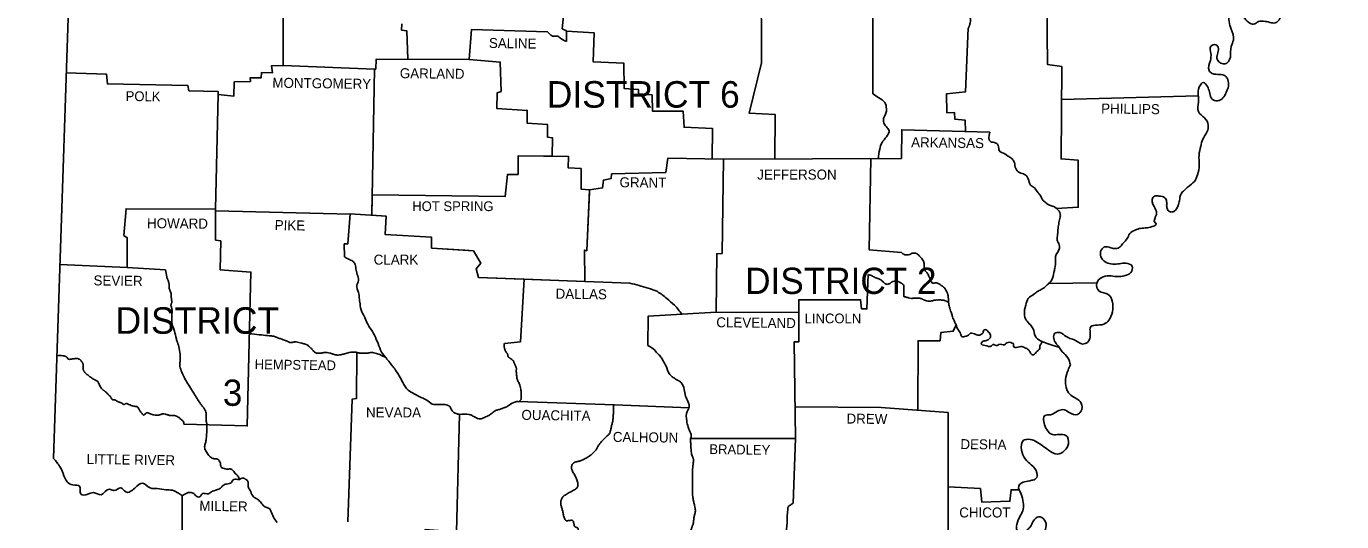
# Model space of a CAD drawing. Extents: x 541267 to 698737, y 790528 to 880942.
# Drawn here: x 637378 to 660525, y 843520 to 852235 of the extents above; entities that cross this region are included whole.
import ezdxf

# ---------------------------------------------------------------- set-up
doc = ezdxf.new("R2010")
doc.units = 0
doc.layers.add('Default', color=7, linetype='Continuous')
doc.layers.add('R_Draft', color=7, linetype='Continuous')

msp = doc.modelspace()

# ---------------------------------------------------------------- linework, layer by layer
at = {"layer": 'Default'}
msp.add_line((643463, 849273), (643456, 848913), dxfattribs=at)
for points in [[(647287, 849322), (647289, 849359), (647141, 849371), (647141, 849731), (646912, 849748), (646920, 849944), (646634, 849948), (646036, 849957), (646032, 849629), (645848, 849629), (645803, 849240), (643463, 849273)], [(647207, 847747), (647203, 848299), (647240, 848287), (647287, 849322)], [(647287, 849322), (647287, 849322)], [(643456, 848913), (643708, 848897), (643692, 848573), (644506, 848528), (644510, 848332), (645097, 848296), (645247, 848287)], [(645247, 848287), (645374, 848066), (645296, 847968), (645333, 847816), (646137, 847787), (647207, 847747)]]:
    msp.add_lwpolyline(points, dxfattribs=at)
at = {"layer": 'R_Draft'}
for p, q in [((643504, 851483), (643456, 848913)), ((655370, 847710), (656219, 847723))]:
    msp.add_line(p, q, dxfattribs=at)
for points in [[(637378, 862535), (638225, 855734), (637857, 844633)], [(641905, 853220), (641899, 851544), (641695, 851540), (641711, 851417), (641515, 851421), (641511, 851331), (641318, 851331), (641323, 851266), (641036, 851258), (641032, 851008), (640754, 851033), (640709, 849019), (639133, 849024), (639096, 848557), (639154, 848516), (639150, 847992), (637970, 848044)], [(651687, 853361), (651696, 852629), (652273, 852616), (652277, 851045)], [(650071, 853173), (650308, 853156), (650313, 851593), (650100, 850705), (650554, 850685), (650550, 849903)], [(648177, 852764), (647882, 852796), (647894, 852686), (647358, 852665), (647342, 852506), (646838, 852477), (646810, 852191), (646884, 852154), (646884, 851966)], [(655508, 849028), (655890, 849052), (655886, 849883), (655587, 849903), (655603, 851528), (655346, 851565), (655338, 852657), (658848, 852682)], [(643986, 852281), (643982, 852170), (644076, 852154), (644094, 851656)], [(646548, 852137), (645210, 852178), (645173, 851651), (643536, 851659), (643530, 851482)], [(646884, 852152), (647370, 852121), (647354, 851610), (647890, 851589), (647898, 851143), (648152, 851123), (648152, 851045), (648389, 851029), (648398, 850742), (648938, 850742), (648954, 850460), (649453, 850435), (649449, 849903)], [(653954, 852203), (653905, 851082), (653570, 851045), (653578, 850714), (653713, 850718), (653717, 850603), (653901, 850583), (653907, 850385)], [(645173, 851651), (645717, 851606), (645734, 851090), (645664, 851065), (645656, 850791), (646192, 850754), (646192, 850529), (646548, 850509), (646552, 850284), (646638, 850272), (646634, 849948)], [(638082, 851417), (638790, 851393), (638806, 851221), (640222, 851192), (640238, 851102), (640754, 851086), (640754, 851033)], [(643504, 851483), (641899, 851544)], [(643530, 851482), (643504, 851483)], [(655598, 850950), (658002, 851010)], [(654331, 850374), (652784, 850415), (652776, 849912), (649646, 849899)], [(643463, 849273), (645803, 849240), (645848, 849629), (646032, 849629), (646036, 849957), (646920, 849944), (646912, 849748), (647141, 849731), (647141, 849371), (647289, 849359), (647287, 849322)], [(647289, 849359), (647518, 849392), (647534, 849531), (647669, 849556), (647677, 849637), (648631, 849666), (648668, 849916), (649646, 849899)], [(649646, 849899), (649621, 848238), (649527, 848234), (649515, 847207)], [(652241, 849909), (652207, 848303), (652776, 848258)], [(647289, 849359), (647240, 848287), (647203, 848299), (647207, 847747)], [(640709, 849019), (640709, 848475), (640799, 848459), (640791, 847952), (641331, 847911), (641265, 845206), (640152, 845235)], [(640709, 848991), (643077, 848929)], [(642980, 848181), (642972, 848406), (643037, 848410), (643078, 848938), (643708, 848897), (643692, 848573), (644506, 848528), (644510, 848332), (645247, 848287), (645374, 848066), (645296, 847968), (645333, 847816), (648001, 847718)], [(639150, 847992), (639829, 847952)], [(646137, 847787), (646073, 846687), (645791, 846654)], [(652195, 847866), (652170, 847264), (652076, 847264), (652060, 847424), (650971, 847424), (650973, 847199)], [(649515, 847207), (648916, 847170)], [(649515, 847207), (650973, 847199)], [(650973, 847199), (650975, 846687), (650890, 846683), (650914, 844985)], [(648919, 847170), (648320, 847133), (648316, 846622)], [(653738, 846982), (653688, 846871), (653472, 846851), (653459, 846703), (653071, 846703), (653066, 845480)], [(643197, 846497), (643188, 845685), (643115, 845676), (643033, 843520)], [(655252, 846691), (655343, 846655), (655448, 846619), (655548, 846593)], [(646032, 845636), (647726, 845574), (649041, 845523)], [(645001, 845406), (644948, 843344), (644396, 843381), (644391, 843229), (643663, 843272)], [(650902, 845541), (652420, 845529), (653598, 845439)], [(653598, 845439), (653598, 842992), (653631, 840642)], [(649065, 844981), (650914, 844985)], [(650914, 844985), (650873, 843847), (650783, 843790)], [(640119, 843974), (640128, 840664), (655125, 840639)], [(653598, 844135), (654167, 844101), (654192, 843864), (654687, 843880), (654707, 844081), (654860, 844081)]]:
    msp.add_lwpolyline(points, dxfattribs=at)
for points in [[(660346, 855747), (660362, 855628), (660293, 855501), (660268, 855374), (660281, 855247), (660150, 855178), (660035, 855096), (660101, 854998), (660223, 854908), (660346, 854838), (660424, 854769), (660444, 854601), (660465, 854494), (660506, 854347), (660522, 854245), (660448, 854122), (660362, 854097), (660272, 854126), (660166, 854134), (660080, 854052), (660019, 853938), (659957, 853823), (659912, 853725), (659867, 853619), (659777, 853496), (659667, 853476), (659536, 853443), (659458, 853353), (659470, 853201), (659544, 853099), (659601, 852972), (659642, 852862), (659622, 852723), (659565, 852620), (659491, 852559), (659458, 852428), (659405, 852330), (659356, 852297), (659258, 852305), (659151, 852326), (659061, 852318), (658975, 852273), (658889, 852301), (658799, 852399), (658726, 852473), (658644, 852502), (658558, 852457), (658542, 852322), (658582, 852183), (658619, 851994), (658582, 851880), (658570, 851691)], [(653909, 852596), (653905, 852586), (653901, 852576), (653896, 852555), (653893, 852534), (653893, 852524), (653893, 852514), (653896, 852492), (653903, 852470), (653913, 852449), (653919, 852438), (653926, 852428), (653931, 852422), (653939, 852418), (653956, 852414), (653972, 852410), (653979, 852406), (653981, 852403), (653983, 852399), (653985, 852394), (653987, 852389), (653993, 852358), (653994, 852338), (653993, 852328), (653991, 852318), (653983, 852276), (653978, 852256), (653975, 852246), (653971, 852236), (653963, 852219), (653954, 852203)], [(646884, 851966), (646777, 852027), (646716, 852064), (646650, 852060), (646597, 852092), (646548, 852137)], [(658570, 851691), (658476, 851573), (658337, 851646), (658337, 851745), (658357, 851847), (658308, 851912), (658222, 851884), (658222, 851757), (658214, 851634), (658190, 851458), (658247, 851405), (658378, 851389), (658472, 851364), (658529, 851270), (658525, 851155), (658480, 851045), (658415, 850955), (658312, 850922), (658231, 850975), (658198, 851082), (658161, 851176), (658091, 851245), (658018, 851168), (658001, 851025), (658005, 850902), (658005, 850734), (658112, 850623), (658177, 850497), (658157, 850382), (658079, 850247), (658046, 850128), (658014, 849969), (658018, 849793), (657989, 849621), (657932, 849506), (657825, 849412), (657756, 849351), (657699, 849290), (657670, 849167), (657649, 849081), (657572, 848979), (657510, 848970), (657461, 849011), (657445, 849081), (657445, 849150), (657412, 849220), (657310, 849249), (657228, 849245), (657191, 849187), (657244, 849028), (657265, 848925), (657236, 848786), (657253, 848770), (657105, 848692), (656987, 848680), (656888, 848651), (656794, 848590), (656749, 848500), (656684, 848426), (656626, 848357), (656549, 848324), (656463, 848340), (656348, 848353), (656283, 848271), (656303, 848152), (656381, 848082), (656496, 848050), (656614, 848058), (656729, 848070), (656835, 848013), (656815, 847902), (656712, 847849), (656561, 847833), (656438, 847845), (656291, 847812), (656217, 847718), (656258, 847575), (656418, 847518), (656491, 847383), (656496, 847256), (656442, 847088), (656369, 847010), (656225, 846978), (656115, 846957), (656099, 846769), (656050, 846675), (655964, 846646), (655841, 846708), (655767, 846736), (655677, 846777), (655563, 846847), (655477, 846834), (655501, 846654), (655509, 846646), (655608, 846511), (655706, 846405), (655751, 846278)], [(652277, 851045), (652379, 850975), (652485, 850894), (652514, 850783), (652506, 850705), (652473, 850640), (652465, 850538), (652514, 850464), (652559, 850403), (652514, 850292), (652436, 850190), (652395, 850075), (652367, 849903)], [(654331, 850374), (654343, 850206), (654441, 850182), (654482, 850137), (654503, 850042), (654572, 850002), (654666, 849944), (654724, 849903), (654765, 849838), (654789, 849731), (654855, 849662), (654945, 849629), (655010, 849551), (655051, 849441), (655117, 849392), (655182, 849306), (655215, 849269), (655272, 849171), (655329, 849122), (655370, 849093), (655436, 849073), (655518, 849019), (655571, 848938), (655571, 848876), (655550, 848782), (655534, 848684), (655526, 848573), (655518, 848475), (655554, 848393), (655534, 848271), (655493, 848205), (655489, 848115), (655477, 847980), (655460, 847902), (655423, 847776), (655370, 847710)], [(642980, 848181), (643045, 848140), (643123, 848103), (643164, 848042), (643180, 847947), (643209, 847845), (643217, 847739), (643193, 847681), (643225, 847551), (643238, 847460), (643250, 847354), (643283, 847211), (643336, 847113), (643385, 846994), (643467, 846867), (643536, 846728), (643569, 846654), (643630, 846503), (643708, 846401), (643831, 846245), (643941, 846086), (644003, 845967), (644097, 845836), (644203, 845771), (644338, 845701), (644424, 845660), (644522, 845590), (644649, 845582), (644743, 845582), (644829, 845545), (644870, 845472), (644944, 845423), (645001, 845406)], [(652776, 848258), (652837, 848217), (652923, 848222), (652981, 848246), (653026, 848242), (653087, 848205), (653128, 848156), (653156, 848119), (653177, 848062), (653177, 848009), (653197, 847935), (653222, 847906), (653255, 847853), (653275, 847804), (653287, 847771), (653332, 847718), (653373, 847722), (653410, 847718), (653459, 847690), (653533, 847632), (653545, 847616), (653594, 847510), (653603, 847444), (653611, 847358), (653627, 847276), (653660, 847186), (653676, 847125), (653713, 847039), (653738, 846982), (653770, 846908), (653819, 846826), (653840, 846777), (653909, 846781), (653959, 846802), (653995, 846834), (654040, 846830), (654089, 846814), (654155, 846802), (654196, 846826), (654216, 846843), (654220, 846879), (654257, 846900), (654298, 846871), (654343, 846806), (654343, 846765), (654327, 846740), (654274, 846708), (654200, 846683), (654179, 846654), (654249, 846622), (654360, 846613), (654388, 846638), (654462, 846618), (654490, 846638), (654589, 846634), (654634, 846667), (654724, 846663), (654752, 846642), (654752, 846605), (654826, 846589), (654879, 846601), (654949, 846581), (655010, 846548), (655043, 846503), (655084, 846454), (655121, 846466), (655149, 846503), (655211, 846568), (655211, 846609), (655227, 846638), (655252, 846691)], [(639829, 847952), (639849, 847829), (639857, 847802), (639867, 847775), (639878, 847749), (639886, 847722), (639889, 847702), (639889, 847681), (639889, 847661), (639890, 847641), (639898, 847610), (639910, 847579), (639921, 847549), (639927, 847518), (639927, 847473), (639930, 847450), (639933, 847428), (639937, 847405), (639939, 847383), (639937, 847370), (639931, 847358), (639926, 847346), (639923, 847334), (639927, 847309), (639934, 847285), (639941, 847260), (639944, 847235), (639939, 847162), (639939, 847100), (639944, 846998), (639949, 846975), (639958, 846953), (639968, 846931), (639976, 846908), (640009, 846773), (640029, 846703), (640062, 846597), (640083, 846466), (640087, 846368), (640085, 846345), (640082, 846323), (640079, 846300), (640079, 846278), (640103, 846176), (640148, 846073), (640205, 845975), (640275, 845865), (640324, 845779), (640385, 845685), (640435, 845607), (640452, 845582), (640471, 845558), (640490, 845534), (640508, 845509), (640541, 845427), (640543, 845398), (640542, 845369), (640540, 845341), (640541, 845312), (640545, 845286), (640550, 845259), (640555, 845233), (640557, 845206), (640553, 845087), (640545, 844981), (640539, 844944), (640530, 844907), (640522, 844870), (640516, 844834), (640537, 844764), (640615, 844662), (640664, 844633), (640685, 844628), (640707, 844627), (640729, 844625), (640750, 844617), (640774, 844590), (640791, 844559), (640797, 844538), (640798, 844514), (640802, 844492), (640807, 844482), (640815, 844473), (640857, 844453), (640901, 844445), (640913, 844444), (640926, 844444), (640951, 844447), (640975, 844446), (640995, 844437), (641040, 844387), (641102, 844322), (641132, 844264)], [(648001, 847718), (648320, 847628), (648483, 847567), (648647, 847448), (648782, 847330), (648916, 847170)], [(652195, 847866), (652214, 847862), (652232, 847856), (652269, 847841), (652282, 847834), (652295, 847827), (652308, 847819), (652322, 847812), (652339, 847806), (652357, 847801), (652375, 847795), (652391, 847788), (652414, 847772), (652436, 847755), (652452, 847742), (652467, 847728), (652482, 847714), (652490, 847708), (652498, 847702), (652515, 847696), (652534, 847697), (652553, 847703), (652571, 847710), (652585, 847718), (652597, 847727), (652610, 847736), (652625, 847743), (652678, 847751), (652719, 847747), (652764, 847722), (652790, 847707), (652803, 847698), (652808, 847692), (652810, 847689), (652813, 847686), (652821, 847659), (652821, 847646), (652821, 847632), (652821, 847571), (652821, 847485), (652824, 847479), (652831, 847476), (652850, 847473), (652900, 847457), (652952, 847448), (652969, 847449), (652987, 847450), (653004, 847451), (653021, 847452), (653054, 847453), (653087, 847452), (653114, 847448), (653127, 847445), (653140, 847440), (653152, 847434), (653163, 847427), (653174, 847421), (653185, 847415), (653218, 847407), (653267, 847399), (653308, 847403), (653325, 847407), (653343, 847413), (653360, 847418), (653377, 847420), (653418, 847420), (653484, 847420), (653504, 847418), (653515, 847417), (653525, 847415), (653569, 847399), (653589, 847387), (653609, 847373)], [(655370, 847710), (655256, 847616), (655182, 847575), (655104, 847518), (655010, 847448), (654965, 847330), (654941, 847166), (654973, 847068), (655047, 846982), (655096, 846912), (655133, 846789), (655223, 846703), (655252, 846691)], [(641304, 846826), (641478, 846810), (641621, 846794), (641677, 846789), (641704, 846786), (641718, 846784), (641732, 846781), (641761, 846773), (641790, 846762), (641846, 846740), (641949, 846703), (641965, 846697), (641981, 846689), (641997, 846681), (642014, 846675), (642041, 846672), (642069, 846677), (642097, 846683), (642125, 846683), (642172, 846674), (642219, 846663), (642273, 846648), (642300, 846639), (642312, 846633), (642325, 846626), (642366, 846593), (642403, 846556), (642415, 846543), (642425, 846529), (642452, 846503), (642475, 846491), (642498, 846484), (642546, 846483), (642565, 846485), (642585, 846489), (642604, 846493), (642624, 846495), (642718, 846487), (642745, 846479), (642771, 846469), (642797, 846460), (642824, 846454), (642846, 846452), (642867, 846452), (642910, 846458), (642980, 846474), (643062, 846495), (643113, 846503), (643138, 846504), (643164, 846503), (643183, 846500), (643203, 846495), (643222, 846490), (643242, 846487), (643293, 846483), (643344, 846483), (643374, 846485), (643403, 846490), (643433, 846494), (643448, 846495), (643463, 846495), (643493, 846491), (643582, 846465), (643640, 846440), (643697, 846415)], [(645791, 846654), (645786, 846616), (645788, 846596), (645791, 846577), (645796, 846558), (645802, 846539), (645810, 846521), (645820, 846503), (645826, 846494), (645834, 846486), (645842, 846479), (645848, 846470), (645852, 846457), (645853, 846443), (645854, 846429), (645857, 846422), (645861, 846417), (645869, 846410), (645879, 846404), (645888, 846399), (645897, 846393), (645905, 846387), (645912, 846381), (645927, 846370), (645940, 846358), (645946, 846351), (645951, 846343), (645959, 846326), (645966, 846309), (645972, 846291), (645979, 846274), (645990, 846252), (645995, 846241), (645998, 846235), (646000, 846229), (646002, 846215), (646001, 846200), (646000, 846186), (646000, 846172), (646002, 846143), (646004, 846114), (646007, 846079), (646009, 846062), (646012, 846045), (646021, 846013), (646035, 845983), (646050, 845953), (646061, 845922), (646073, 845873), (646081, 845832), (646086, 845762), (646086, 845742), (646087, 845721), (646086, 845701), (646086, 845691), (646086, 845681), (646082, 845669), (646074, 845656), (646052, 845635)], [(648316, 846622), (648410, 846560), (648488, 846478), (648545, 846417), (648582, 846347), (648631, 846266), (648700, 846110), (648762, 846057), (648848, 846004), (648901, 845967), (648954, 845848), (648979, 845730), (649024, 845623), (649044, 845541), (649007, 845460), (648999, 845296), (649024, 845185), (649056, 845104), (649077, 845009), (649065, 844981)], [(637917, 846439), (637958, 846443), (638000, 846442), (638040, 846437), (638073, 846429), (638088, 846418), (638102, 846399), (638117, 846382), (638135, 846376), (638172, 846380), (638237, 846388), (638252, 846390), (638268, 846390), (638283, 846388), (638299, 846384), (638312, 846378), (638323, 846370), (638334, 846359), (638344, 846347), (638356, 846332), (638367, 846316), (638375, 846300), (638380, 846282), (638381, 846267), (638379, 846251), (638377, 846236), (638376, 846221), (638380, 846196), (638385, 846181), (638391, 846167), (638409, 846143), (638458, 846102), (638511, 846061), (638560, 846028), (638571, 846022), (638583, 846017), (638606, 846006), (638627, 845993), (638642, 845975), (638650, 845959), (638683, 845893), (638701, 845865), (638712, 845852), (638724, 845840), (638736, 845831), (638749, 845824), (638762, 845816), (638773, 845807), (638826, 845750), (638851, 845726), (638862, 845712), (638871, 845697), (638880, 845681), (638886, 845675), (638892, 845668), (638902, 845664), (638914, 845665), (638926, 845666), (638937, 845664), (638952, 845656), (638967, 845645), (638982, 845635), (638998, 845627), (639009, 845624), (639021, 845621), (639032, 845618), (639043, 845615), (639056, 845608), (639068, 845598), (639079, 845589), (639092, 845582), (639105, 845583), (639117, 845591), (639129, 845598), (639142, 845599), (639157, 845593), (639172, 845586), (639187, 845580), (639203, 845574), (639285, 845550), (639296, 845548), (639308, 845547), (639325, 845544), (639327, 845543), (639330, 845541), (639347, 845525), (639359, 845505), (639370, 845484), (639376, 845473), (639383, 845464), (639408, 845430), (639421, 845414), (639436, 845398), (639443, 845395), (639451, 845397), (639467, 845412), (639484, 845429), (639493, 845434), (639502, 845435), (639532, 845427), (639562, 845416), (639593, 845405), (639624, 845398), (639663, 845394), (639702, 845394), (639720, 845398), (639737, 845405), (639754, 845411), (639772, 845415), (639825, 845410), (639850, 845405), (639874, 845398), (639898, 845391), (639923, 845386), (639938, 845385), (639954, 845386), (639969, 845387), (639984, 845386), (640050, 845361), (640111, 845312), (640152, 845259), (640152, 845235)], [(655751, 846278), (655710, 846184), (655665, 846020), (655677, 845881), (655739, 845762), (655837, 845697), (655943, 845603), (655935, 845460), (655874, 845406), (655730, 845443), (655620, 845492), (655526, 845464), (655399, 845402), (655305, 845390), (655309, 845194), (655436, 845054), (655546, 845054), (655673, 845038), (655718, 844891), (655644, 844768), (655522, 844707), (655366, 844780), (655256, 844858), (655145, 844932), (655006, 844969), (654928, 844952), (654891, 844780), (654957, 844625), (655063, 844518), (655162, 844379), (655145, 844277), (655072, 844248), (654941, 844220), (654863, 844179), (654842, 844146), (654883, 844007), (654920, 843856), (654920, 843741), (654875, 843635), (654806, 843471), (654814, 843365), (654863, 843315), (654924, 843332), (655006, 843389), (655059, 843455), (655104, 843536), (655190, 843606), (655297, 843545), (655321, 843418), (655260, 843307), (655174, 843258), (655067, 843217), (654990, 843127), (655010, 843021), (655072, 842964), (655223, 842992), (655325, 843037), (655383, 843094), (655452, 843164), (655489, 843234), (655542, 843307), (655636, 843328), (655681, 843266), (655665, 843127), (655608, 842996), (655530, 842886), (655444, 842808), (655338, 842640), (655358, 842485), (655399, 842358), (655456, 842260), (655554, 842280), (655665, 842292), (655730, 842239), (655722, 842125), (655640, 842014), (655563, 841908), (655522, 841761), (655538, 841658), (655538, 841564), (655505, 841462), (655448, 841405), (655297, 841409), (655137, 841425), (655051, 841376), (655067, 841237), (655162, 841134), (655227, 841081), (655321, 840967), (655362, 840873), (655350, 840791), (655293, 840721), (655125, 840639)], [(645848, 845550), (645955, 845619), (646032, 845636)], [(647713, 845575), (647710, 845447), (647707, 845384), (647705, 845352), (647702, 845320), (647690, 845257), (647673, 845194), (647662, 845136), (647655, 845107), (647651, 845093), (647648, 845086), (647645, 845079), (647632, 845060), (647617, 845044), (647583, 845014), (647550, 844981), (647518, 844948), (647456, 844874), (647442, 844853), (647430, 844829), (647418, 844806), (647403, 844784), (647350, 844727), (647280, 844670), (647211, 844629), (647133, 844592), (647112, 844585), (647091, 844581), (647069, 844578), (647047, 844572), (647013, 844554), (646999, 844542), (646992, 844535), (646986, 844527), (646975, 844503), (646971, 844477), (646982, 844428), (646998, 844394), (647017, 844359), (647035, 844325), (647051, 844289), (647076, 844224), (647081, 844205), (647085, 844185), (647086, 844165), (647084, 844146), (647055, 844101), (646990, 844064), (646912, 844019), (646843, 843978), (646826, 843965), (646813, 843948), (646802, 843929), (646793, 843909), (646782, 843862), (646785, 843815), (646793, 843787), (646802, 843759), (646810, 843732), (646818, 843704), (646824, 843672), (646830, 843639), (646846, 843581), (646860, 843555), (646871, 843545), (646877, 843540), (646884, 843536), (646894, 843534), (646904, 843536), (646914, 843539), (646924, 843540), (646934, 843541), (646943, 843542), (646961, 843545), (646980, 843544), (646989, 843542), (646994, 843539), (646998, 843536), (647004, 843527), (647006, 843516), (647010, 843495), (647027, 843442), (647039, 843428), (647057, 843420), (647076, 843411), (647088, 843397), (647091, 843387), (647092, 843377), (647094, 843366), (647096, 843356), (647112, 843317), (647133, 843279), (647146, 843262), (647161, 843247), (647194, 843225), (647240, 843209), (647334, 843180), (647383, 843168), (647390, 843165), (647403, 843145), (647409, 843105), (647415, 843068), (647423, 843055), (647436, 843049), (647469, 843050), (647501, 843054), (647550, 843062), (647592, 843060), (647612, 843053), (647622, 843048), (647632, 843041), (647654, 843018), (647669, 842992), (647679, 842972), (647687, 842951), (647696, 842931), (647706, 842910), (647728, 842879), (647739, 842867)], [(645848, 845550), (645819, 845537), (645766, 845517), (645705, 845496), (645648, 845480), (645574, 845431), (645517, 845390), (645439, 845353), (645365, 845329), (645275, 845357), (645226, 845386), (645173, 845406), (645001, 845406)], [(649065, 844981), (649068, 844917), (649072, 844854), (649081, 844727), (649088, 844696), (649101, 844666), (649113, 844635), (649116, 844620), (649118, 844604), (649116, 844572), (649112, 844539), (649108, 844506), (649105, 844473), (649101, 844347), (649101, 844232), (649101, 844122), (649101, 844007), (649110, 843925), (649116, 843895), (649123, 843866), (649131, 843836), (649138, 843806), (649148, 843751), (649151, 843723), (649150, 843696), (649146, 843669), (649139, 843643), (649132, 843616), (649126, 843590), (649123, 843565), (649121, 843540), (649118, 843516), (649114, 843491), (649106, 843467), (649098, 843442), (649089, 843418), (649081, 843393), (649052, 843283), (649020, 843139), (649007, 843092), (648999, 843069), (648991, 843045), (648978, 843020), (648963, 842995), (648948, 842972), (648934, 842947), (648924, 842925), (648915, 842902), (648906, 842879), (648897, 842857), (648884, 842842), (648867, 842830), (648851, 842817), (648844, 842809), (648839, 842800), (648830, 842751), (648831, 842702), (648834, 842679), (648838, 842657), (648841, 842634), (648844, 842612), (648843, 842591), (648840, 842571), (648836, 842550), (648835, 842530), (648843, 842490), (648864, 842452), (648878, 842435), (648892, 842420), (648922, 842399)], [(637857, 844633), (637975, 844478), (638024, 844367), (638094, 844224), (638196, 844167), (638315, 844146), (638339, 844007), (638462, 844003), (638560, 844031), (638695, 843995), (638839, 844093), (638921, 844068), (639039, 844117), (639129, 844044), (639285, 844109), (639424, 844199), (639555, 844113), (639682, 844101), (639833, 844081), (639952, 844072), (640058, 844019), (640112, 843982), (640119, 843974)], [(640119, 843974), (640263, 844036), (640324, 844015), (640377, 843962), (640439, 843962), (640471, 844011), (640533, 844015), (640582, 844011), (640635, 844044), (640680, 844064), (640741, 844085), (640786, 844101), (640827, 844146), (640901, 844183), (640987, 844212), (641012, 844252), (641052, 844269), (641134, 844265), (641187, 844289), (641232, 844269), (641273, 844240), (641282, 844134), (641314, 844077), (641363, 843974), (641433, 843921), (641498, 843868), (641523, 843835), (641593, 843774), (641654, 843753), (641683, 843708), (641728, 843602), (641793, 843508)], [(650783, 843790), (650771, 843663), (650767, 843545), (650759, 843430), (650756, 843387), (650757, 843366), (650759, 843344), (650767, 843319), (650781, 843296), (650796, 843274), (650808, 843250), (650836, 843160), (650865, 843082), (650922, 842980), (650935, 842960), (650949, 842941), (650963, 842922), (650975, 842902), (650996, 842847), (650998, 842818), (650992, 842792), (650959, 842734), (650944, 842713), (650928, 842691), (650912, 842670), (650898, 842648), (650891, 842611), (650900, 842568), (650906, 842527), (650894, 842493), (650885, 842486), (650876, 842479), (650857, 842468), (650838, 842457), (650820, 842444), (650774, 842402), (650750, 842381), (650726, 842362), (650673, 842325), (650615, 842288), (650599, 842274), (650584, 842257), (650569, 842239), (650554, 842223), (650532, 842207), (650508, 842193), (650485, 842179), (650464, 842162), (650446, 842137), (650431, 842111), (650416, 842084), (650399, 842059), (650381, 842038), (650364, 842018), (650325, 841981), (650263, 841941), (650242, 841927), (650220, 841915), (650188, 841895), (650178, 841887), (650163, 841871), (650153, 841850), (650141, 841806), (650130, 841768), (650120, 841730), (650113, 841692), (650112, 841654), (650117, 841599), (650124, 841544), (650141, 841445), (650139, 841415), (650130, 841384), (650122, 841353), (650120, 841323), (650141, 841188), (650161, 841081), (650194, 840987), (650239, 840881), (650266, 840831), (650296, 840783), (650348, 840713), (650404, 840647)]]:
    msp.add_spline(points, degree=3, dxfattribs=at)

# ---------------------------------------------------------------- texts
at = {"layer": 'Default'}
msp.add_text('HOT SPRING', height=171.9, dxfattribs=at).set_placement((644169, 848984))
at = {"layer": 'R_Draft'}
for s, height, rotation, p in [('SALINE', 176, 359.1492, (645517, 851855)), ('GARLAND', 176, 359.3658, (643950, 851323)), ('MONTGOMERY', 176, 359.2944, (641707, 851155)), ('POLK', 171.8, 359.2152, (639125, 850922)), ('PHILLIPS', 175.9, 359.318, (656291, 850701)), ('ARKANSAS', 175.9, 359.2678, (652948, 850108)), ('GRANT', 176, 359.4032, (647816, 849404)), ('HOWARD', 176, 359.5145, (639502, 848684)), ('PIKE', 175.9, 359.0452, (641748, 848651)), ('SEVIER', 176, 359.4271, (638560, 847677)), ('DALLAS', 175.9, 359.2462, (646691, 847444)), ('CLEVELAND', 176, 359.3377, (649519, 846941)), ('HEMPSTEAD', 171.8, 359.1885, (641396, 846204)), ('OUACHITA', 176, 359.2043, (646090, 845312)), ('DREW', 175.9, 359.2258, (651810, 845247)), ('CALHOUN', 176, 359.3634, (647698, 844924)), ('BRADLEY', 171.8, 359.1449, (649396, 844711)), ('DESHA', 175.9, 359.3704, (653815, 844797)), ('LITTLE RIVER', 175.98, 359.1697, (638438, 844535)), ('MILLER', 175.9, 359.132, (640422, 843712))]:
    msp.add_text(s, height=height, rotation=rotation, dxfattribs=at).set_placement(p)
for s, height, p in [('DISTRICT 6', 466.5, (646536, 850804)), ('JEFFERSON', 176, (650239, 849539)), ('CLARK', 176, (643491, 848042)), ('DISTRICT 2', 462.4, (650028, 847526)), ('DISTRICT', 466.5, (638949, 846826)), ('LINCOLN', 171.9, (651074, 847010)), ('3', 462, (640836, 845558)), ('NEVADA', 176, (643356, 845353)), ('CHICOT', 176, (653795, 843594))]:
    msp.add_text(s, height=height, dxfattribs=at).set_placement(p)

doc.saveas('drawing.dxf')
